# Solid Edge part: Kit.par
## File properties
Sűrűség: 0,000 kg/m^3
Pontosság: 0,990
Author: ahadarics
Last saved by: psaghy
Revision: 77
Username: ahadarics
Dokumentum tartalom típus: 0
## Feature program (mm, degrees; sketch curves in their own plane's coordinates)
base feature "unnamed BaseFeature 1"
sketch for "Furat_1" plane through (0, 0, -150.6) normal (0, 0, -1) x-axis (-0.707107, 0.707107, 0)
  hole centre (0, 77.7817) bore radius 5.053
hole "Furat_1" nominal diameter 12 finite  VBottomAngle = 118 deg; ThreadDepth = 20 mm
sketch for "unnamed Hole 1" plane through (0, 0, -150.6) normal (0, 0, -1) x-axis (-0.707107, 0.707107, 0)
  hole centre (-77.7817, 0) bore radius 5.053
hole "unnamed Hole 1" finite
sketch for "unnamed Hole 2" plane through (0, 0, -150.6) normal (0, 0, -1) x-axis (-0.707107, 0.707107, 0)
  hole centre (0, -77.7817) bore radius 5.053
hole "unnamed Hole 2" finite
sketch for "unnamed Hole 3" plane through (0, 0, -150.6) normal (0, 0, -1) x-axis (-0.707107, 0.707107, 0)
  hole centre (77.7817, 0) bore radius 5.053
hole "unnamed Hole 3" finite
pattern "unnamed Pattern 1" of "Furat_1", "unnamed Hole 1", "unnamed Hole 2", "unnamed Hole 3"
sketch for "Furat_5" plane through (67, -0.0076, -126.0988) normal (1, 0, 0) x-axis (0, 0, 1)
hole "Furat_5" diameter 20.955 finite  ThreadDepth = 25 mm
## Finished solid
Body 1: solid body, 597 faces, 1401 edges, 865 vertices, 7 internal voids.
  Faces by surface: cylinder 190, plane 181, torus 64, cone 62, sphere 54, spline 30, spun 8, swept 8
  Edges by curve: circle 478, curve on surface 459, line 424, spline 37, ellipse 3
Bounding box of the edges (mm; curved faces can reach further): 134.000 x 134.000 x 93.000, from (-67, -67, -196.6) to (67, 67, -103.6).
Cylindrical faces by radius (mm): R0.5 x4, R0.5232 x2, R0.5479 x2, R0.5758 x1, R0.6133 x1, R0.638 x1, R0.6383 x2, R0.6612 x1, R0.8412 x2, R0.8728 x2, R0.8941 x1, R0.9225 x1, R0.9466 x1, R0.9543 x1, R0.978 x1, R1 x33, R1.0002 x2, R1.0012 x7, R1.0017 x1, R1.0187 x1, R1.095 x1, R1.1067 x1, R1.3671 x1, R1.5039 x1, R1.5591 x1, R1.5808 x1, R1.6101 x1, R1.6481 x1, R1.7807 x1, R1.8842 x1, R1.9083 x3, R2 x12, R2.001 x12, R2.0033 x12, R2.0042 x12, R2.2009 x1, R2.5714 x2, R2.6379 x2, R5.053 x8, R6 x5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
Conical faces (half-angle, radius in mm at the cone's reference point): 0.2415 deg R1.0092 x1, 1 deg R29.5 x6, 1 deg R47.75 x6, 1.6538 deg R17.75 x1, 3.5477 deg R18.7454 x1, 5.1705 deg R16.4 x1, 8.3742 deg R16.0032 x1, 13.2989 deg R17.1846 x1, 14.7738 deg R16.7787 x1, 15 deg R27.5 x1, 25.0169 deg R20.31 x1, 30 deg R6.1443 x1, 30 deg R18.8557 x2, 30 deg R19.1443 x1, 30 deg R29.25 x1, 45 deg R3.75 x1, 45 deg R3.875 x1, 45 deg R6.3 x8, 45 deg R8.75 x8, 45 deg R10.91 x1, 45 deg R16.15 x2, 45 deg R21.35 x1, 50.7743 deg R54.75 x1, 54.9406 deg R44.1774 x6, 54.9406 deg R56.75 x3, 59 deg R5.053 x4
Toroidal faces (ring radius, tube radius in mm): R1.5 r0.5 x1, R2 r1 x6, R5.7 r0.3 x1, R8.95 r0.2 x4, R9.65 r0.5 x4, R13 r1 x8, R16 r0.5 x1, R16.3 r0.3 x1, R16.3088 r0.3 x1, R17.4279 r0.25 x1, R18.2464 r0.5 x1, R20.8 r0.2 x1, R25.7327 r1 x1, R27.5 r1 x1, R29.5 r0.5 x1, R29.5 r1 x1, R30.5 r0.5 x1, R31.4654 r2 x6, R39.973 r2 x6, R45.7681 r2 x6, R66 r1 x3, R67.3563 r1 x2, R70 r1 x6
Spherical faces by radius (mm): R1 x18, R2 x36
Planar faces by outward normal: +x 22, +y 8, +z 26, -x 4, -y 7, -z 44, oblique 70
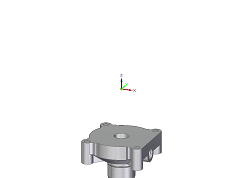
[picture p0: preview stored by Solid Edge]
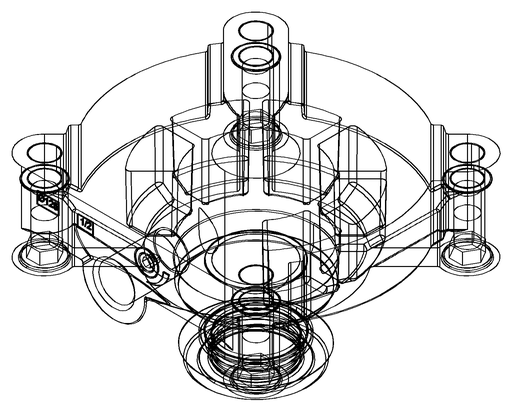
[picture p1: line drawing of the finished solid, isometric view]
